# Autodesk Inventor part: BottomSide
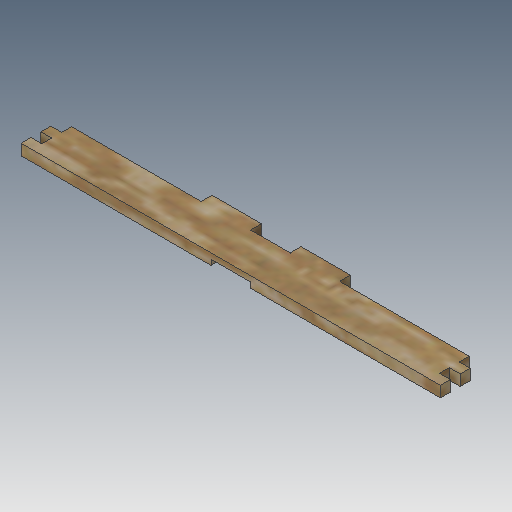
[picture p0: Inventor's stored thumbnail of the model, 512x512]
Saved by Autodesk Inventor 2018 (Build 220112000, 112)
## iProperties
Created: 2018-05
Part Number: BottomSide
Material: Generic
Document SubType Name: Modeling
Designer: arivu
Density: 1 g/cm^3
Appearance: Default
Author: arivu
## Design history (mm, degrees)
derived "WaterTank.ipt"
feature "Solid34::WaterTank.ipt" dims "d0" = 10
tag "TaggingFeature1"
body "Solid1"
